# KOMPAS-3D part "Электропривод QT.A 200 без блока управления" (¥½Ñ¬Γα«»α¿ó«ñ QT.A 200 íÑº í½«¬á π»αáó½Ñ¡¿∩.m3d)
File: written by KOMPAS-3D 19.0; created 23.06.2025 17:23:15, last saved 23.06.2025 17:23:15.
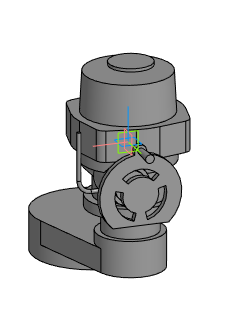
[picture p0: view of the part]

Document properties: Автор: Евгений; Полное имя файла: E:\Dendor Работа Сачек\3D для проектировщиков\3.5 Тип QT.А Электропривод\stp_Электропривод QT.A без блока управления\Электропривод QT.A 200 без блока управления.m3d

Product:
- Part/product: Электропривод QT.A 200 без блока управления

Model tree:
1. Операция без истории:1  (labels: Электропривод QT.A 200 без блока управления)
